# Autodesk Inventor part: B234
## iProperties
Author: Administrator
Revision Number: A
Created: 2001-03
Part Number: B234
Document SubType Name: Modeling
Designer: Administrator
Description: BRACKET W/HORIZONTAL HOLES
Control State: 0
Master: False
Checked Out: False
PropertySet Name: Design Tracking Control
Shininess: 20.0
PropertySet Name: _Private Model Information
Density: 0.0
Volumn: 0.0
Area: 0.0
PropertySet Name: Model Information
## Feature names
1. Derived Body1 [Tagging]
